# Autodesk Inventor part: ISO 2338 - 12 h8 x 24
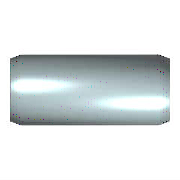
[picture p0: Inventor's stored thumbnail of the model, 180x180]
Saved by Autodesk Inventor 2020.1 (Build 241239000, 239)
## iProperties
Created: 2019-01
Part Number: ISO 2338 - 12 h8 x 24
Material: Edelstahl, austenitisch
Description: Zylinderstift
Document SubType Name: Modeling
Standard: ISO 2338
Designer: lutzd
Standard Revision: Second edition 1997-11-01
Standards Organization: ISO
Language: de-DE
Size Designation: 12 h8 x 24
Categories: <MemberInstance><Categories><Category DisplayName="Verbindungselemente" InternalName="e4da775c-781d-43d5-af7c-5136215cf5a6" Mnemonic="FSTN"><Category DisplayNam
Mass: 21.2284 g
Surface Area: 10.7904 cm^2
Volume: 2.65355 cm^3
Density: 8 g/cm^3
Appearance: Halbpoliert
IsCustomPart: 0
Author: lutzd
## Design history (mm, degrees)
sketch "Skizze"
  geometry: C1 r 6 at (0, 0); 1 further point
  constraints: 1 centre point, 1 coincident
  dimensions: "d1" = 12 diameter of C1 (= NND)
extrude "Körper" new body sketch "Skizze" distance "d2" = 24 (= NLG); taper "d3" = 0 deg
chamfer "Skizze2" distance "d8" = 2.5 (= PHH); stored, may be unused: angle "d9" = 15 deg (= FAWI), second distance "d12" = 2.5 (= PHH)
body "Solid1"
chamfer "Fase1" distance "d4" = 2.5 (= PHH); stored, may be unused: angle "d5" = 15 deg (= FAWI), second distance "d11" = 2.5 (= PHH)
other parameters: "NND" = 12 [user parameter; used in 1 equation term], "NLG" = 24 [user parameter; used in 1 equation term], "PHH" = 2.5 [user parameter; used in 4 equation terms], "FAWI" = 15 deg [user parameter; used in 2 equation terms], "d13" = 0, "d15" = 0, "d16" = 0, "KAH" = 0 [user parameter]
